Omron CX-Programmer project NuevoProyecto (CX-Programmer 9.50)

# PLC NewPLC1: CP1L-E EM

## Program P20_1a (cyclic task 0)
Local symbols
A 0.04 BOOL  ; Selección tolva A
B 0.05 BOOL  ; Selección tolva B
De 0.07 BOOL  ; Selección CIN3 derecha
EVA 100.04 BOOL  ; Electroválvula tolva A
EVB 100.05 BOOL  ; Electroválvula tolva B
Em 15.00 BOOL  ; Emergencia memorizada
Etapa_0 10.00 BOOL
Etapa_1 10.01 BOOL
Etapa_10 10.08 BOOL
Etapa_11 10.09 BOOL
Etapa_12 10.10 BOOL
Etapa_13 10.11 BOOL
Etapa_14 10.12 BOOL
Etapa_2 10.02 BOOL
Etapa_3 10.03 BOOL
Etapa_4 10.04 BOOL
Etapa_5 10.05 BOOL
Etapa_6 10.06 BOOL
Etapa_7 10.07 BOOL
H_1 100.06 BOOL  ; Lámpara marcha
H_2 100.07 BOOL  ; Lámpara paro
H_3 101.00 BOOL  ; Lámpara emergencia
H_4 101.01 BOOL  ; Lámpara RT1
H_5 101.02 BOOL  ; Lámpara RT2
H_6 101.03 BOOL  ; Lámpara RT3
Iz 0.06 BOOL  ; Selección CIN3 izquierda
K1 100.00 BOOL  ; Contactor CIN1
K2 100.01 BOOL  ; Contactor CIN2
K3D 100.03 BOOL  ; Contactor derecha CIN3
K3I 100.02 BOOL  ; Contactor izquierda CIN3
PE 0.02 BOOL  ; Pulsador de emergencia
PM 0.00 BOOL  ; Pulsador de marcha
PP 0.01 BOOL  ; Pulsador de paro
PR 0.03 BOOL  ; Pulsador de rearme
RT 15.01 BOOL  ; RT=RT1+RT2+RT3
RT1 0.08 BOOL  ; Relé térmico CIN1
RT2 0.09 BOOL  ; Relé térmico CIN2
RT3 0.10 BOOL  ; Relé térmico CIN3
RTm 15.02 BOOL  ; Relés térmicos memorizados

### Section Sección1_Programa_principal
; Etapas 0 ... 7

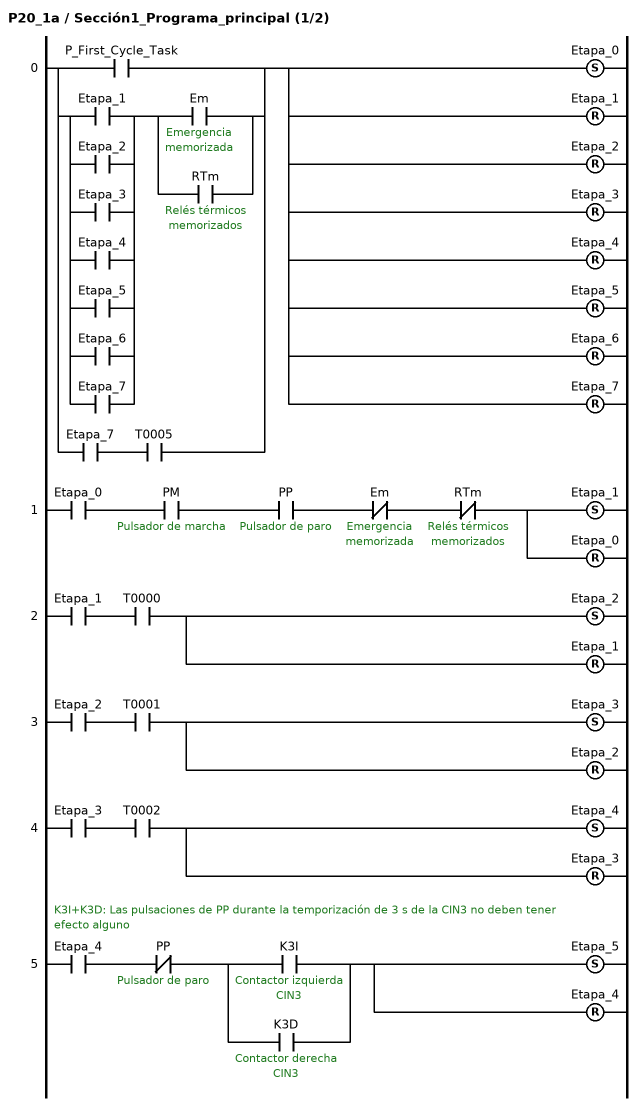
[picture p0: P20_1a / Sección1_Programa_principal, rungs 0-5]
; rung 0
LD P_First_Cycle_Task
LD Etapa_1
OR Etapa_2
OR Etapa_3
OR Etapa_4
OR Etapa_5
OR Etapa_6
OR Etapa_7
LD Em  ; Emergencia memorizada
OR RTm  ; Relés térmicos memorizados
ANDLD
ORLD
LD Etapa_7
AND T0005
ORLD
SET Etapa_0
RSET Etapa_1
RSET Etapa_2
RSET Etapa_3
RSET Etapa_4
RSET Etapa_5
RSET Etapa_6
RSET Etapa_7
; rung 1
LD Etapa_0
AND PM  ; Pulsador de marcha
AND PP  ; Pulsador de paro
ANDNOT Em  ; Emergencia memorizada
ANDNOT RTm  ; Relés térmicos memorizados
SET Etapa_1
RSET Etapa_0
; rung 2
LD Etapa_1
AND T0000
SET Etapa_2
RSET Etapa_1
; rung 3
LD Etapa_2
AND T0001
SET Etapa_3
RSET Etapa_2
; rung 4
LD Etapa_3
AND T0002
SET Etapa_4
RSET Etapa_3
; rung 5: K3I+K3D: Las pulsaciones de PP durante la temporización de 3 s de la CIN3 no deben tener efecto alguno
LD Etapa_4
ANDNOT PP  ; Pulsador de paro
LD K3I  ; Contactor izquierda CIN3
OR K3D  ; Contactor derecha CIN3
ANDLD
SET Etapa_5
RSET Etapa_4

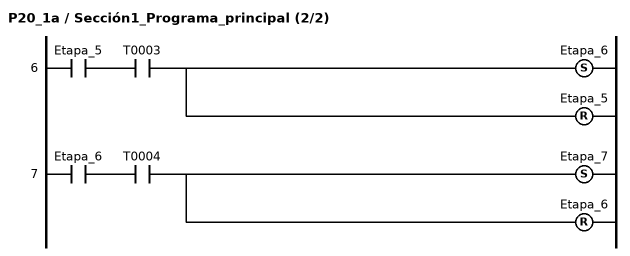
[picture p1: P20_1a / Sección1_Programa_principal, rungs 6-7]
; rung 6
LD Etapa_5
AND T0003
SET Etapa_6
RSET Etapa_5
; rung 7
LD Etapa_6
AND T0004
SET Etapa_7
RSET Etapa_6

### Section Sección2_Disparo_térmicos
; Etapas 10 ... 14

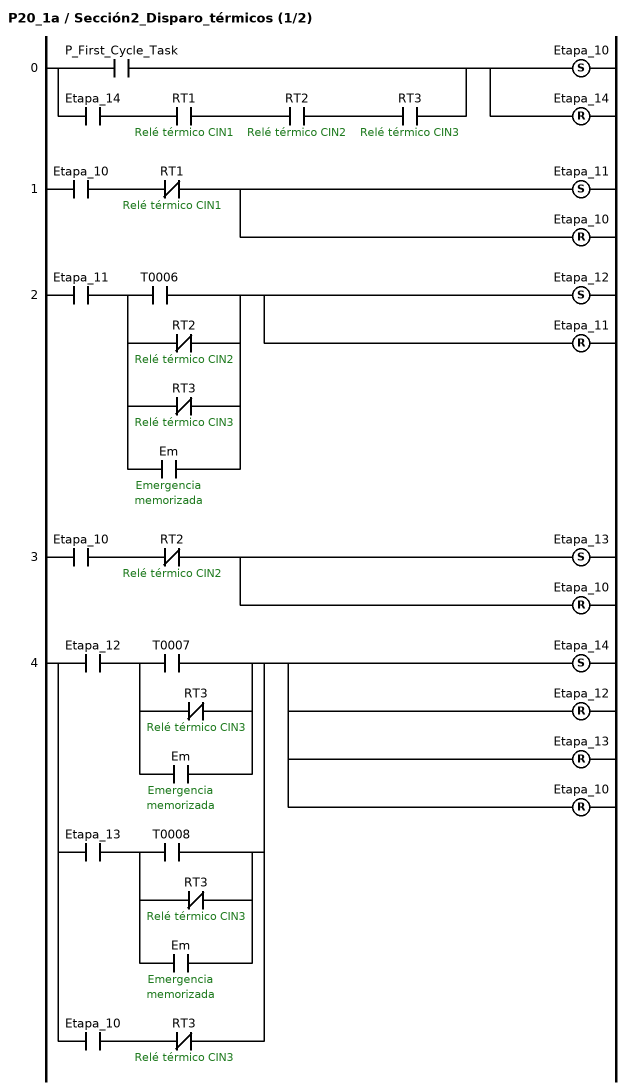
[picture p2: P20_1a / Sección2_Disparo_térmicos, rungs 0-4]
; rung 0
LD P_First_Cycle_Task
LD Etapa_14
AND RT1  ; Relé térmico CIN1
AND RT2  ; Relé térmico CIN2
AND RT3  ; Relé térmico CIN3
ORLD
SET Etapa_10
RSET Etapa_14
; rung 1
LD Etapa_10
ANDNOT RT1  ; Relé térmico CIN1
SET Etapa_11
RSET Etapa_10
; rung 2
LD Etapa_11
LD T0006
ORNOT RT2  ; Relé térmico CIN2
ORNOT RT3  ; Relé térmico CIN3
OR Em  ; Emergencia memorizada
ANDLD
SET Etapa_12
RSET Etapa_11
; rung 3
LD Etapa_10
ANDNOT RT2  ; Relé térmico CIN2
SET Etapa_13
RSET Etapa_10
; rung 4
LD Etapa_12
LD T0007
ORNOT RT3  ; Relé térmico CIN3
OR Em  ; Emergencia memorizada
ANDLD
LD Etapa_13
LD T0008
ORNOT RT3  ; Relé térmico CIN3
OR Em  ; Emergencia memorizada
ANDLD
ORLD
LD Etapa_10
ANDNOT RT3  ; Relé térmico CIN3
ORLD
SET Etapa_14
RSET Etapa_12
RSET Etapa_13
RSET Etapa_10

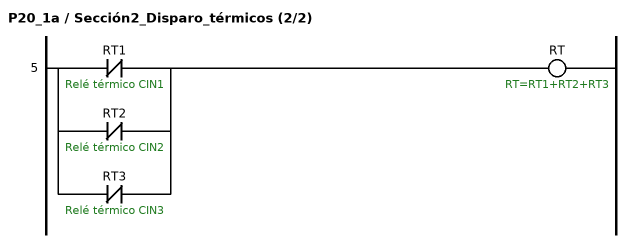
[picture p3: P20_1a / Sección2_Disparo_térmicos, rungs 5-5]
; rung 5
LDNOT RT1  ; Relé térmico CIN1
ORNOT RT2  ; Relé térmico CIN2
ORNOT RT3  ; Relé térmico CIN3
OUT RT  ; RT=RT1+RT2+RT3

### Section Sección3_Temporizadores

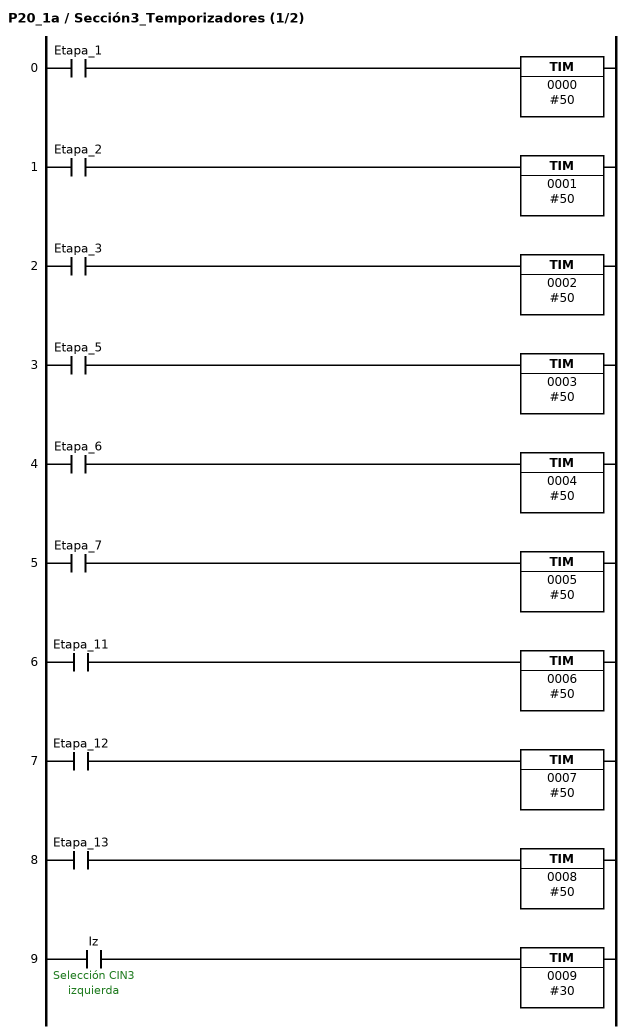
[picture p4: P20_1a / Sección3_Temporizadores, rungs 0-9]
; rung 0
LD Etapa_1
TIM 0000 #50
; rung 1
LD Etapa_2
TIM 0001 #50
; rung 2
LD Etapa_3
TIM 0002 #50
; rung 3
LD Etapa_5
TIM 0003 #50
; rung 4
LD Etapa_6
TIM 0004 #50
; rung 5
LD Etapa_7
TIM 0005 #50
; rung 6
LD Etapa_11
TIM 0006 #50
; rung 7
LD Etapa_12
TIM 0007 #50
; rung 8
LD Etapa_13
TIM 0008 #50
; rung 9
LD Iz  ; Selección CIN3 izquierda
TIM 0009 #30

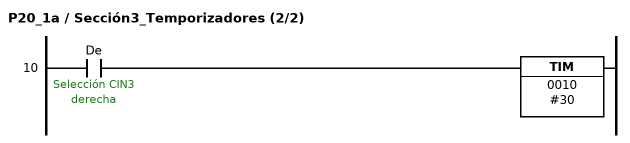
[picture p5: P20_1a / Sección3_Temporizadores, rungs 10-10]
; rung 10
LD De  ; Selección CIN3 derecha
TIM 0010 #30

### Section Sección4_Memorizaciones

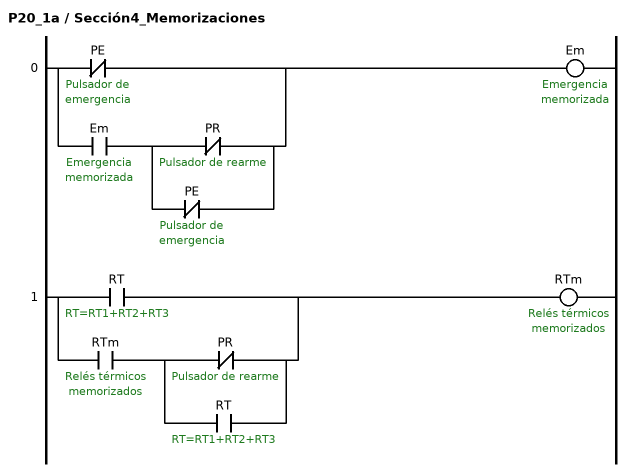
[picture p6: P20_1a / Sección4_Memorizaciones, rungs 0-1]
; rung 0
LDNOT PE  ; Pulsador de emergencia
LD Em  ; Emergencia memorizada
LDNOT PR  ; Pulsador de rearme
ORNOT PE  ; Pulsador de emergencia
ANDLD
ORLD
OUT Em  ; Emergencia memorizada  // Em=PE+Em·(PR·PE')'=PE+Em·(PR'+PE)
; rung 1
LD RT  ; RT=RT1+RT2+RT3
LD RTm  ; Relés térmicos memorizados
LDNOT PR  ; Pulsador de rearme
OR RT  ; RT=RT1+RT2+RT3
ANDLD
ORLD
OUT RTm  ; Relés térmicos memorizados  // RTm=RT+RTm·(PR·RT')'=RT+RTm·(PR'+RT)

### Section Sección5_Salidas

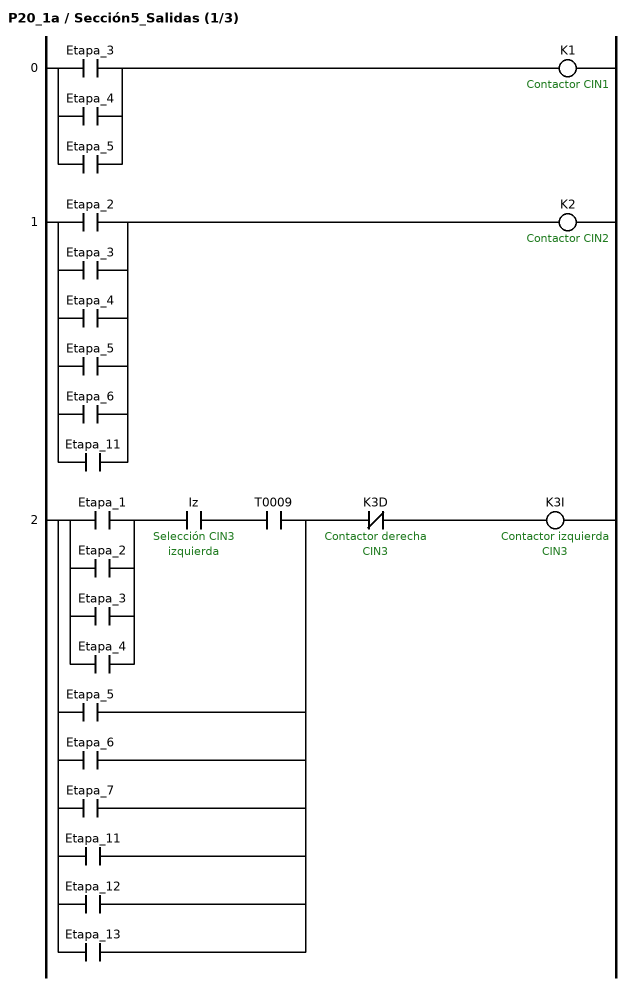
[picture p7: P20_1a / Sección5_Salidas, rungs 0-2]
; rung 0
LD Etapa_3
OR Etapa_4
OR Etapa_5
OUT K1  ; Contactor CIN1
; rung 1
LD Etapa_2
OR Etapa_3
OR Etapa_4
OR Etapa_5
OR Etapa_6
OR Etapa_11
OUT K2  ; Contactor CIN2
; rung 2
LD Etapa_1
OR Etapa_2
OR Etapa_3
OR Etapa_4
AND Iz  ; Selección CIN3 izquierda
AND T0009
OR Etapa_5
OR Etapa_6
OR Etapa_7
OR Etapa_11
OR Etapa_12
OR Etapa_13
ANDNOT K3D  ; Contactor derecha CIN3
OUT K3I  ; Contactor izquierda CIN3

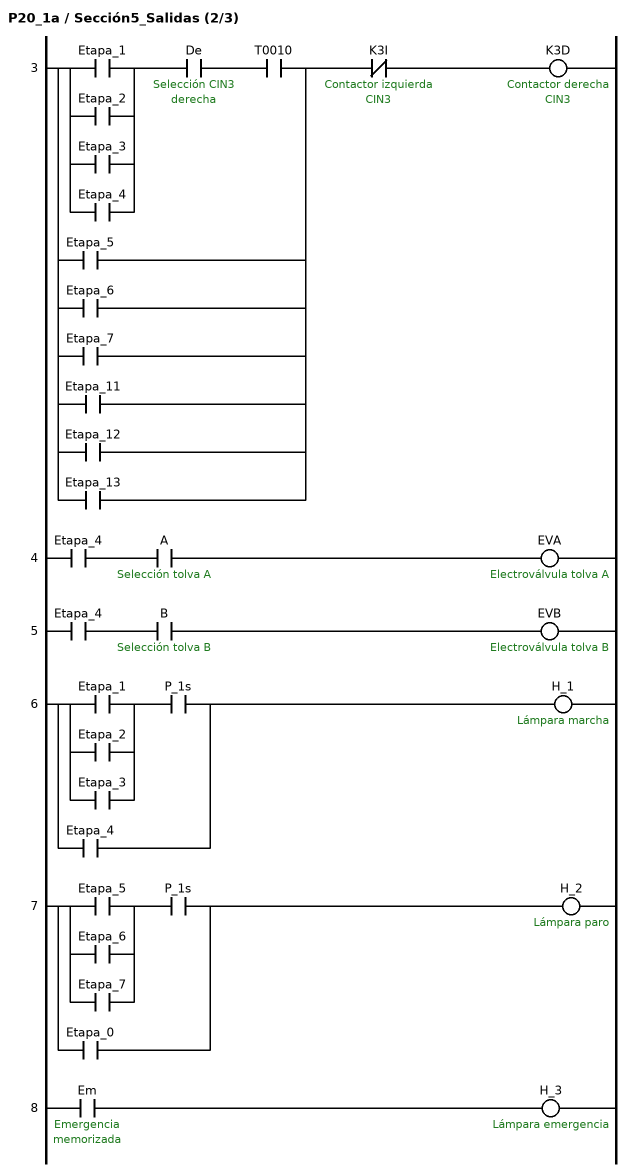
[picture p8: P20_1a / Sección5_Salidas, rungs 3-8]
; rung 3
LD Etapa_1
OR Etapa_2
OR Etapa_3
OR Etapa_4
AND De  ; Selección CIN3 derecha
AND T0010
OR Etapa_5
OR Etapa_6
OR Etapa_7
OR Etapa_11
OR Etapa_12
OR Etapa_13
ANDNOT K3I  ; Contactor izquierda CIN3
OUT K3D  ; Contactor derecha CIN3
; rung 4
LD Etapa_4
AND A  ; Selección tolva A
OUT EVA  ; Electroválvula tolva A
; rung 5
LD Etapa_4
AND B  ; Selección tolva B
OUT EVB  ; Electroválvula tolva B
; rung 6
LD Etapa_1
OR Etapa_2
OR Etapa_3
AND P_1s
OR Etapa_4
OUT H_1  ; Lámpara marcha
; rung 7
LD Etapa_5
OR Etapa_6
OR Etapa_7
AND P_1s
OR Etapa_0
OUT H_2  ; Lámpara paro
; rung 8
LD Em  ; Emergencia memorizada
OUT H_3  ; Lámpara emergencia

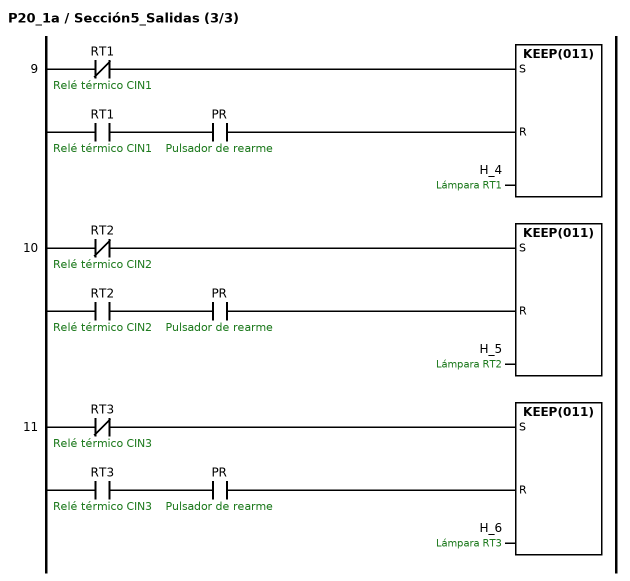
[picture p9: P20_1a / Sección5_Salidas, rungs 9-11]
; rung 9
LDNOT RT1  ; Relé térmico CIN1
LD RT1  ; Relé térmico CIN1
AND PR  ; Pulsador de rearme
KEEP(011) H_4  ; Lámpara RT1
; rung 10
LDNOT RT2  ; Relé térmico CIN2
LD RT2  ; Relé térmico CIN2
AND PR  ; Pulsador de rearme
KEEP(011) H_5  ; Lámpara RT2
; rung 11
LDNOT RT3  ; Relé térmico CIN3
LD RT3  ; Relé térmico CIN3
AND PR  ; Pulsador de rearme
KEEP(011) H_6  ; Lámpara RT3

### Section Sección6_END
; rung 0: Fin de programa
END(001)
